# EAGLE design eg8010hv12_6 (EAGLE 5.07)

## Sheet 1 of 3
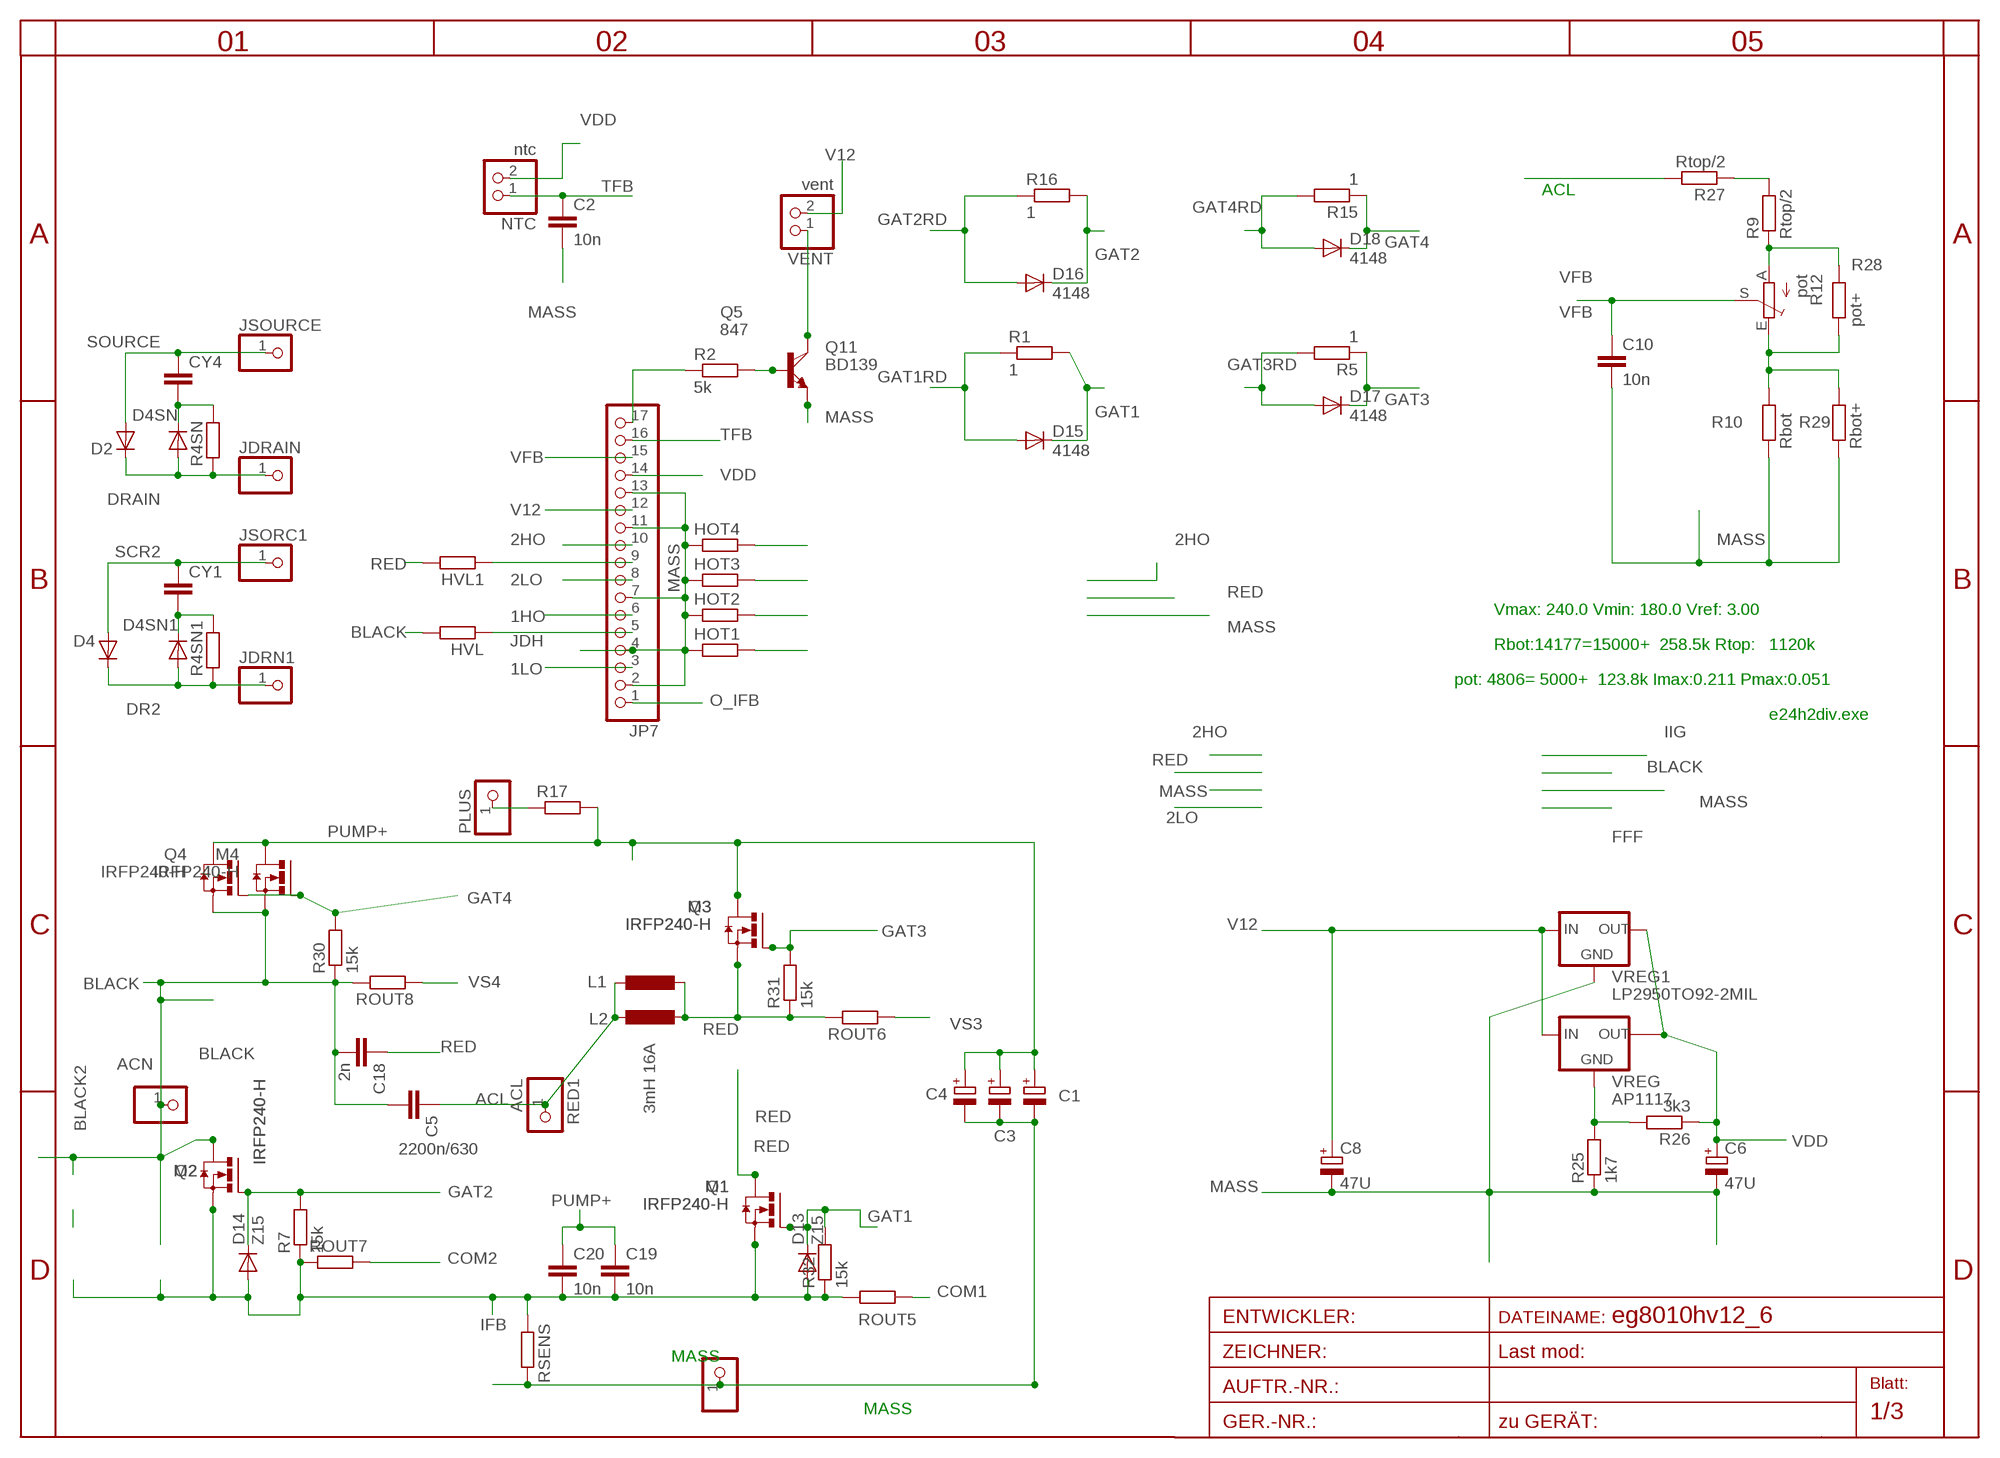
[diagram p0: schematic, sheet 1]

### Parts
BLACK2  ACN  PINHD-1X12MM3  [1X2MM3]
C1  CPOL-EUE5-13  [E5-13]
C2  10n  C-EUC0805  [C0805]
C3  CPOL-EUE5-13  [E5-13]
C4  CPOL-EUE5-13  [E5-13]
C5  2200n/630  C-EU275-173X316  [C275-173X316]
C6  47U  CPOL-EUSMCA  [SMC_A]
C8  47U  CPOL-EUSMCA  [SMC_A]
C10  10n  C-EUC0805  [C0805]
C18  2n  C-EU050-024X044  [C050-024X044]
C19  10n  C-EU050-024X044  [C050-024X044]
C20  10n  C-EU050-024X044  [C050-024X044]
CY1  CXXC10B5  [XC10B5]
CY4  CXXC10B5  [XC10B5]
D2  DIODE-TO220V  [TO220ACS]
D4  DIODE-TO220V  [TO220ACS]
D4SN  DIODE-P1-10  [P1-10]
D4SN1  DIODE-P1-10  [P1-10]
D13  Z15  DIODE-MINIMELF  [MINIMELF]
D14  Z15  DIODE-MINIMELF  [MINIMELF]
D15  4148  DIODE-MINIMELF  [MINIMELF]
D16  4148  DIODE-MINIMELF  [MINIMELF]
D17  4148  DIODE-MINIMELF  [MINIMELF]
D18  4148  DIODE-MINIMELF  [MINIMELF]
HOT1  R-EU_R0805  [R0805]
HOT2  R-EU_R0805  [R0805]
HOT3  R-EU_R0805  [R0805]
HOT4  R-EU_R0805  [R0805]
HVL  R-EU_R1005  [R1005]
HVL1  R-EU_R1005  [R1005]
JDRAIN  PINHD-1X11MM0  [1X1MM0]
JDRN1  PINHD-1X11MM0  [1X1MM0]
JP7  PINHD-1X17  [1X17]
JSORC1  PINHD-1X11MM0  [1X1MM0]
JSOURCE  PINHD-1X11MM0  [1X1MM0]
L1  L-EU4.13  [0204/13]
L2  3mH 16A  L-EURNG  [RING]
M1  IRFP240-H  [TO247BH]
M2  IRFP240-H  [TO247BH]
M3  IRFP240-H  [TO247BH]
M4  IRFP240-H  [TO247BH]
MINUS  PINHD-1X12MM3  [1X2MM3]
NTC  ntc  PINHD-1X2STR  [1X02]
PLUS  PINHD-1X12MM3  [1X2MM3]
Q1  IRFP240-H  [TO247BH]
Q2  IRFP240-H  [TO247BH]
Q3  IRFP240-H  [TO247BH]
Q4  IRFP240-H  [TO247BH]
Q5  847  BC847SMD  [SOT23]
Q11  BD139  [TO126AV]
R1  1  R-EU_R2512  [R2512]
R2  5k  R-EU_R0805  [R0805]
R4SN  R-EU_0207/10  [0207/10]
R4SN1  R-EU_0207/10  [0207/10]
R5  1  R-EU_R2512  [R2512]
R7  15k  R-EU_R1206  [R1206]
R9  Rtop/2  R-EU_R1206  [R1206]
R10  Rbot  R-EU_R0805  [R0805]
R12  pot  TRIM_EU-B64Y  [B64Y]
R15  1  R-EU_R2512  [R2512]
R16  1  R-EU_R2512  [R2512]
R17  R-EU_0309/10  [0309/10]
R25  1k7  R-EU_R0805  [R0805]
R26  3k3  R-EU_R0805  [R0805]
R27  Rtop/2  R-EU_R1206  [R1206]
R28  pot+  R-EU_R0805  [R0805]
R29  Rbot+  R-EU_R0805  [R0805]
R30  15k  R-EU_R1206  [R1206]
R31  15k  R-EU_R1206  [R1206]
R32  15k  R-EU_R1206  [R1206]
RED1  ACL  PINHD-1X12MM3  [1X2MM3]
ROUT5  R-EU_R2512  [R2512]
ROUT6  R-EU_R2512  [R2512]
ROUT7  R-EU_R2512  [R2512]
ROUT8  R-EU_R2512  [R2512]
RSENS  R-EU_WIRE  [WIRE]
VENT  vent  PINHD-1X2STR  [1X02]
VREG  AP1117  [SOT223]
VREG1  LP2950TO92-2MIL  [TO92-2MIL]

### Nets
1HO: HOT2.2 JP7.6 ; also sheet 3
1LO: HOT1.2 JP7.3 ; also sheet 3
2HO: HOT4.2 JP7.10 ; also sheet 3
2LO: HOT3.2 JP7.8 ; also sheet 3
ACL: C5.1 L1.1 L2.2 R27.2 RED1.1
BLACK: BLACK2.1 C5.2 C18.2 HVL.2 M2.D M4.S Q2.D Q4.S R30.1 ROUT8.2
COM1: ROUT5.1 ; also sheet 3
COM2: ROUT7.2 ; also sheet 3
DFG: HVL1.1 JP7.9
DR2: D4.C D4SN1.A JDRN1.1 R4SN1.1
DRAIN: D2.C D4SN.A JDRAIN.1 R4SN.1
GAT1: D13.C D15.C M1.G Q1.G R1.2 R32.2
GAT1RD: D15.A R1.1 ; also sheet 3
GAT2: D14.C D16.C M2.G Q2.G R7.2 R16.2
GAT2RD: D16.A R16.1 ; also sheet 3
GAT3: D17.C M3.G Q3.G R5.1 R31.2
GAT3RD: D17.A R5.2 ; also sheet 3
GAT4: D18.C M4.G Q4.G R15.1 R30.2
GAT4RD: D18.A R15.2 ; also sheet 3
IFB: C19.2 C20.2 D13.A D14.A M1.S M2.S Q1.S Q2.S R7.1 R32.1 ROUT5.2 ROUT7.1 RSENS.1 ; also sheet 2,3
JDH: HVL.1 JP7.5
MASS: C1.- C2.2 C3.- C4.- C6.- C8.- C10.2 HOT1.1 HOT2.1 HOT3.1 HOT4.1 JP7.2 JP7.4 JP7.7 JP7.11 JP7.13 MINUS.1 Q5.2(E) Q11.E R10.1 R25.1 R29.1 RSENS.2 VREG1.2(GND) ; also sheet 2,3
N$1: Q5.3(C) Q11.C VENT.1
N$2: Q5.1(B) Q11.B R2.2
N$3: JP7.17 R2.1
N$5: PLUS.1 R17.1
N$17: R25.2 R26.2 VREG.1(GND)
N$23: R9.2 R27.1
N$29: R10.2 R12.E R28.1 R29.2
N$30: R9.1 R12.A R28.2
O_IFB: JP7.1 ; also sheet 3
PUMP+: C1.+ C3.+ C4.+ C19.1 C20.1 M3.D M4.D Q3.D Q4.D R17.2 ; also sheet 2
RED: C18.1 HVL1.2 L1.2 L2.1 M1.D M3.S Q1.D Q3.S R31.1 ROUT6.2
SCR2: CY1.1 D4.A JSORC1.1
SNUB1: CY1.2 D4SN1.C R4SN1.2
SNUB2: CY4.2 D4SN.C R4SN.2
SOURCE: CY4.1 D2.A JSOURCE.1
TFB: C2.1 JP7.16 NTC.1 ; also sheet 2
V12: C8.+ JP7.12 VENT.2 VREG1.3(IN) VREG.3(IN) ; also sheet 2,3
VDD: C6.+ JP7.14 NTC.2 R26.1 VREG1.1(OUT) VREG.4(TAB) ; also sheet 2,3
VFB: C10.1 JP7.15 R12.S ; also sheet 2
VS3: ROUT6.1 ; also sheet 3
VS4: ROUT8.1 ; also sheet 3
Unconnected: VREG.2(OUT)

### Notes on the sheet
- Vmax: 240.0 Vmin: 180.0 Vref: 3.00
- Rbot:14177=15000+  258.5k Rtop:   1120k
- pot: 4806= 5000+  123.8k Imax:0.211 Pmax:0.051
- e24h2div.exe

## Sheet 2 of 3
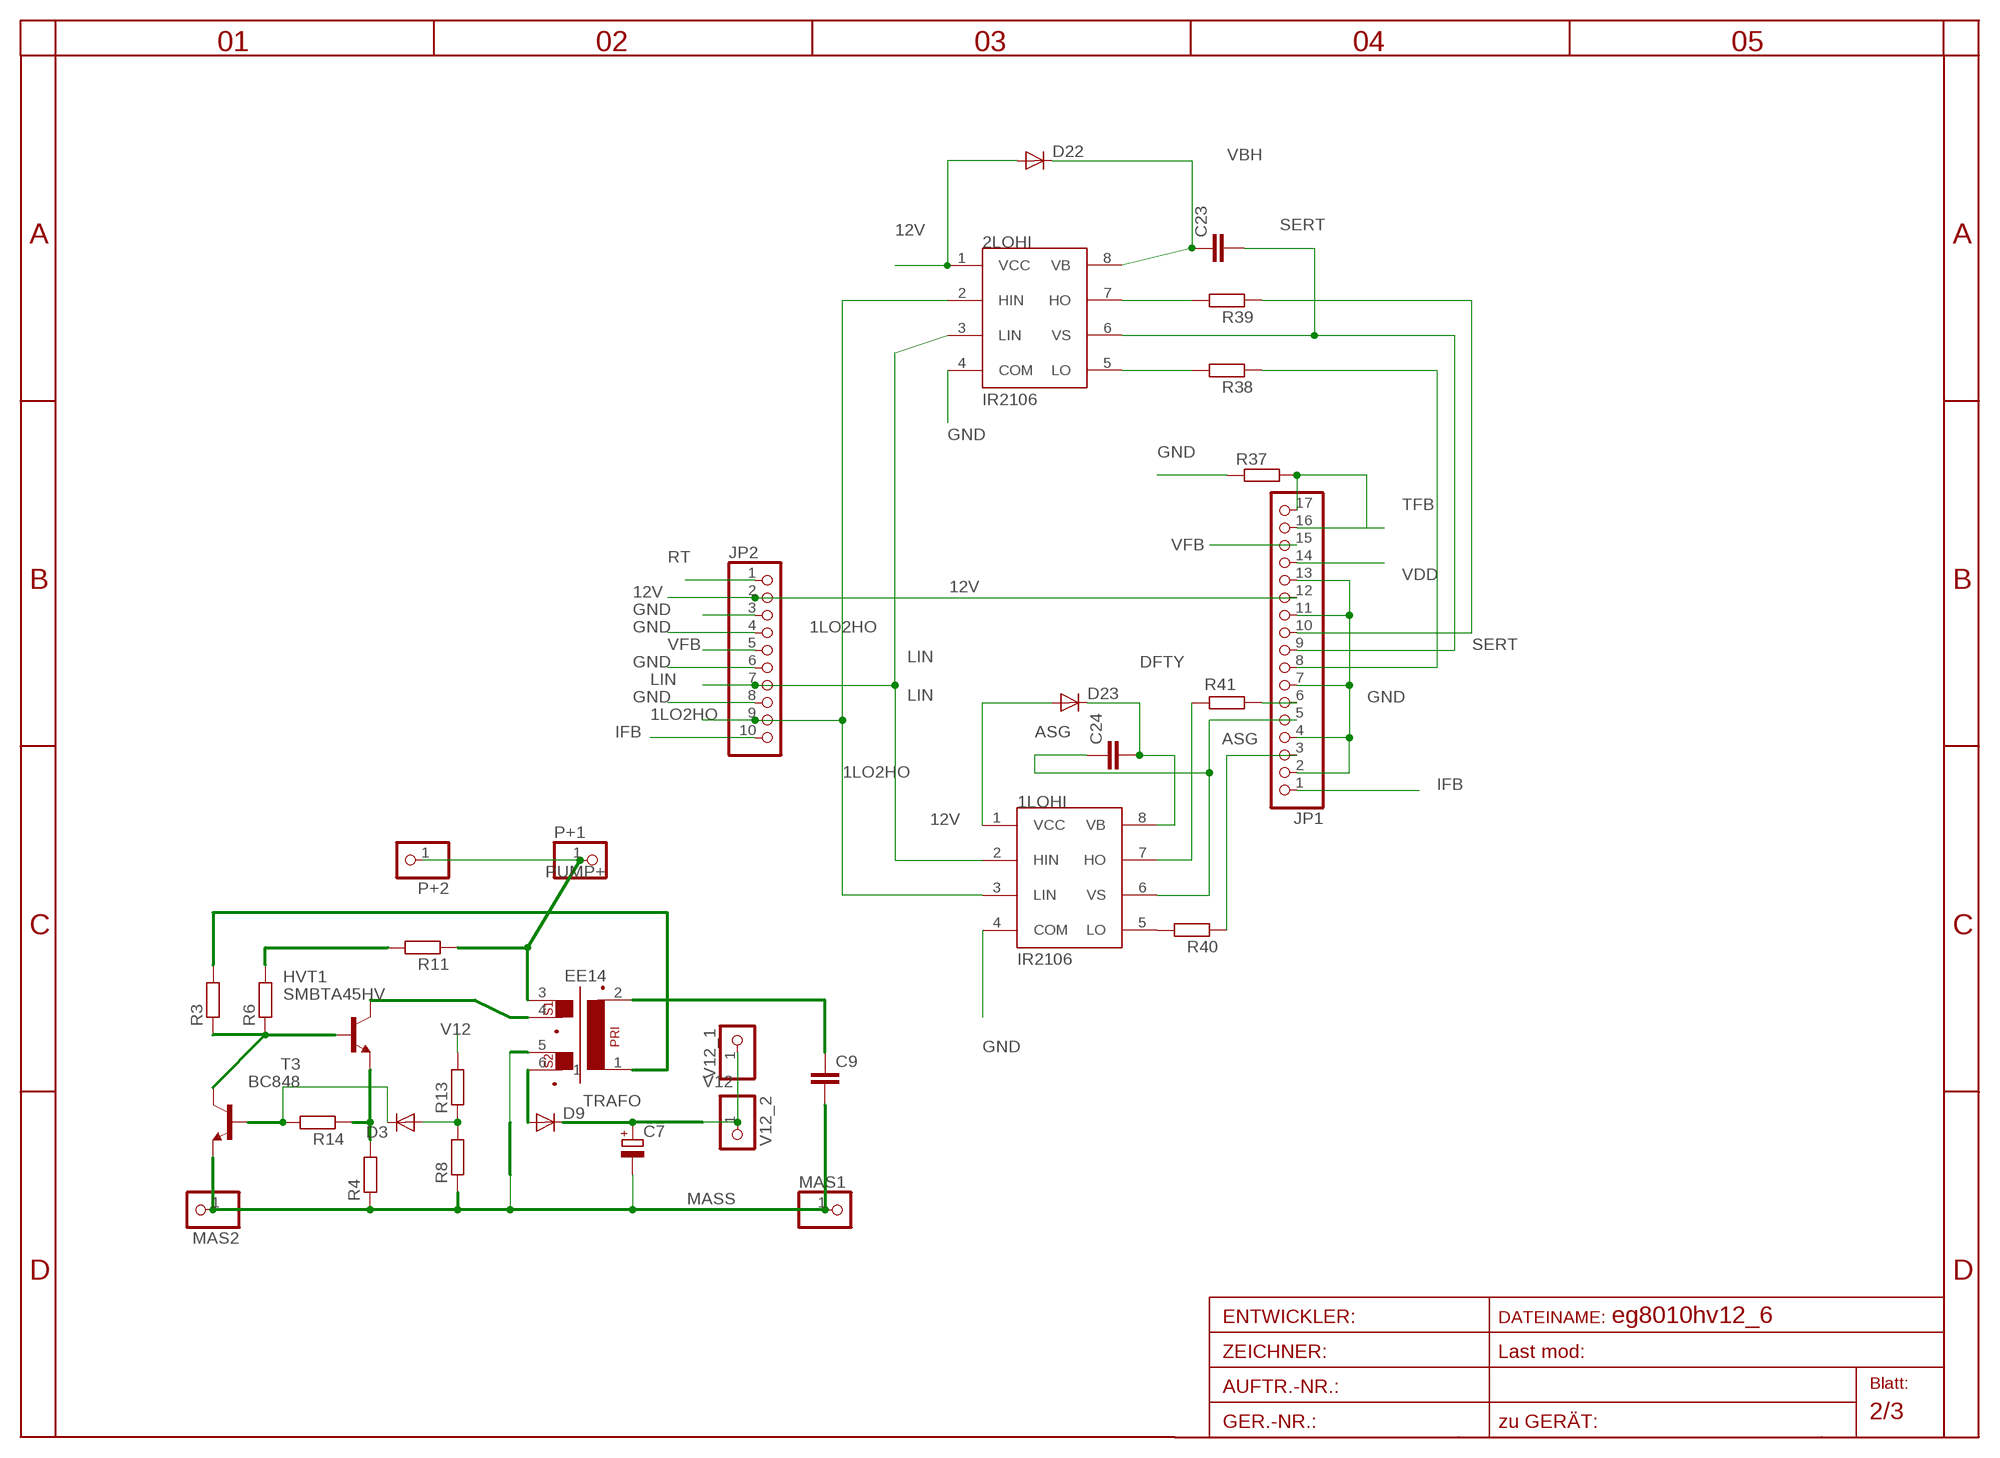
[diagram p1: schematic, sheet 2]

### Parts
1LOHI  IR2106  [SO8-5]
2LOHI  IR2106  [SO8-5]
C7  CPOL-EUSMCA  [SMC_A]
C9  C-EUC0805  [C0805]
C23  C-EUC1206  [C1206]
C24  C-EUC1206  [C1206]
D3  DIODE-MINIMELF  [MINIMELF]
D9  DIODE-SMA-DO214  [SMA-DO214AC]
D22  DIODE-SMA-DO214  [SMA-DO214AC]
D23  DIODE-SMA-DO214  [SMA-DO214AC]
HVT1  SMBTA45HV  [SOT23HV]
JP1  PINHD-1X17  [1X17]
JP2  PINHD-1X100X05  [1X10]
MAS1  PINHD-1X11X0.4  [1X01]
MAS2  PINHD-1X11X0.4  [1X01]
P+1  PINHD-1X11X0.4  [1X01]
P+2  PINHD-1X11X0.4  [1X01]
R3  R-EU_R0805  [R0805]
R4  R-EU_R0805  [R0805]
R6  R-EU_R1206  [R1206]
R8  R-EU_R0805  [R0805]
R11  R-EU_R1206  [R1206]
R13  R-EU_R0805  [R0805]
R14  R-EU_R0805  [R0805]
R37  R-EU_0204/2V  [0204V]
R38  R-EU_R1206  [R1206]
R39  R-EU_R1206  [R1206]
R40  R-EU_R1206  [R1206]
R41  R-EU_R1206  [R1206]
T3  BC848  [SOT23]
TRAFO  EE14  [EE14]
V12_1  PINHD-1X11X0.4  [1X01]
V12_2  PINHD-1X11X0.4  [1X01]

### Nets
1LO2HO: 1LOHI.3(LIN) 2LOHI.2(HIN) JP2.9
12V: 1LOHI.1(VCC) 2LOHI.1(VCC) D22.A D23.A JP1.12 JP2.2
A: D9.A TRAFO.6
ASG: 1LOHI.6(VS) C24.1 JP1.5
B1C2: HVT1.1(B) R3.1 R6.1 T3.C
BT1: D3.C R14.2 T3.B
C1: HVT1.3(C) TRAFO.4
DFTY: 1LOHI.8(VB) C24.2 D23.K(C)
EB: HVT1.2(E) R4.2 R14.1
GND: 1LOHI.4(COM) 2LOHI.4(COM) JP1.2 JP1.4 JP1.7 JP1.11 JP1.13 JP2.3 JP2.4 JP2.6 JP2.8 R37.1
IFB: JP1.1 JP2.10 ; also sheet 1,3
LIN: 1LOHI.2(HIN) 2LOHI.3(LIN) JP2.7
MASS: C7.- C9.2 MAS1.1 MAS2.1 R4.1 R8.1 T3.E TRAFO.5 ; also sheet 1,3
N$6: R3.2 TRAFO.1
N$7: C9.1 TRAFO.2
N$8: R6.2 R11.2
N$10: D3.A R8.2 R13.1
N$15: JP1.3 R40.1
N$19: 1LOHI.7(HO) R41.2
N$21: JP1.8 R38.1
N$27: JP1.10 R39.1
N$32: 2LOHI.5(LO) R38.2
N$33: 2LOHI.7(HO) R39.2
N$34: JP1.6 R41.1
N$35: 1LOHI.5(LO) R40.2
PUMP+: P+1.1 P+2.1 R11.1 TRAFO.3 ; also sheet 1
RT: JP2.1
SERT: 2LOHI.6(VS) C23.2 JP1.9
TFB: JP1.16 JP1.17 R37.2 ; also sheet 1
V12: C7.+ D9.K(C) R13.2 V12_1.1 V12_2.1 ; also sheet 1,3
VBH: 2LOHI.8(VB) C23.1 D22.K(C)
VDD: JP1.14 ; also sheet 1,3
VFB: JP1.15 JP2.5 ; also sheet 1

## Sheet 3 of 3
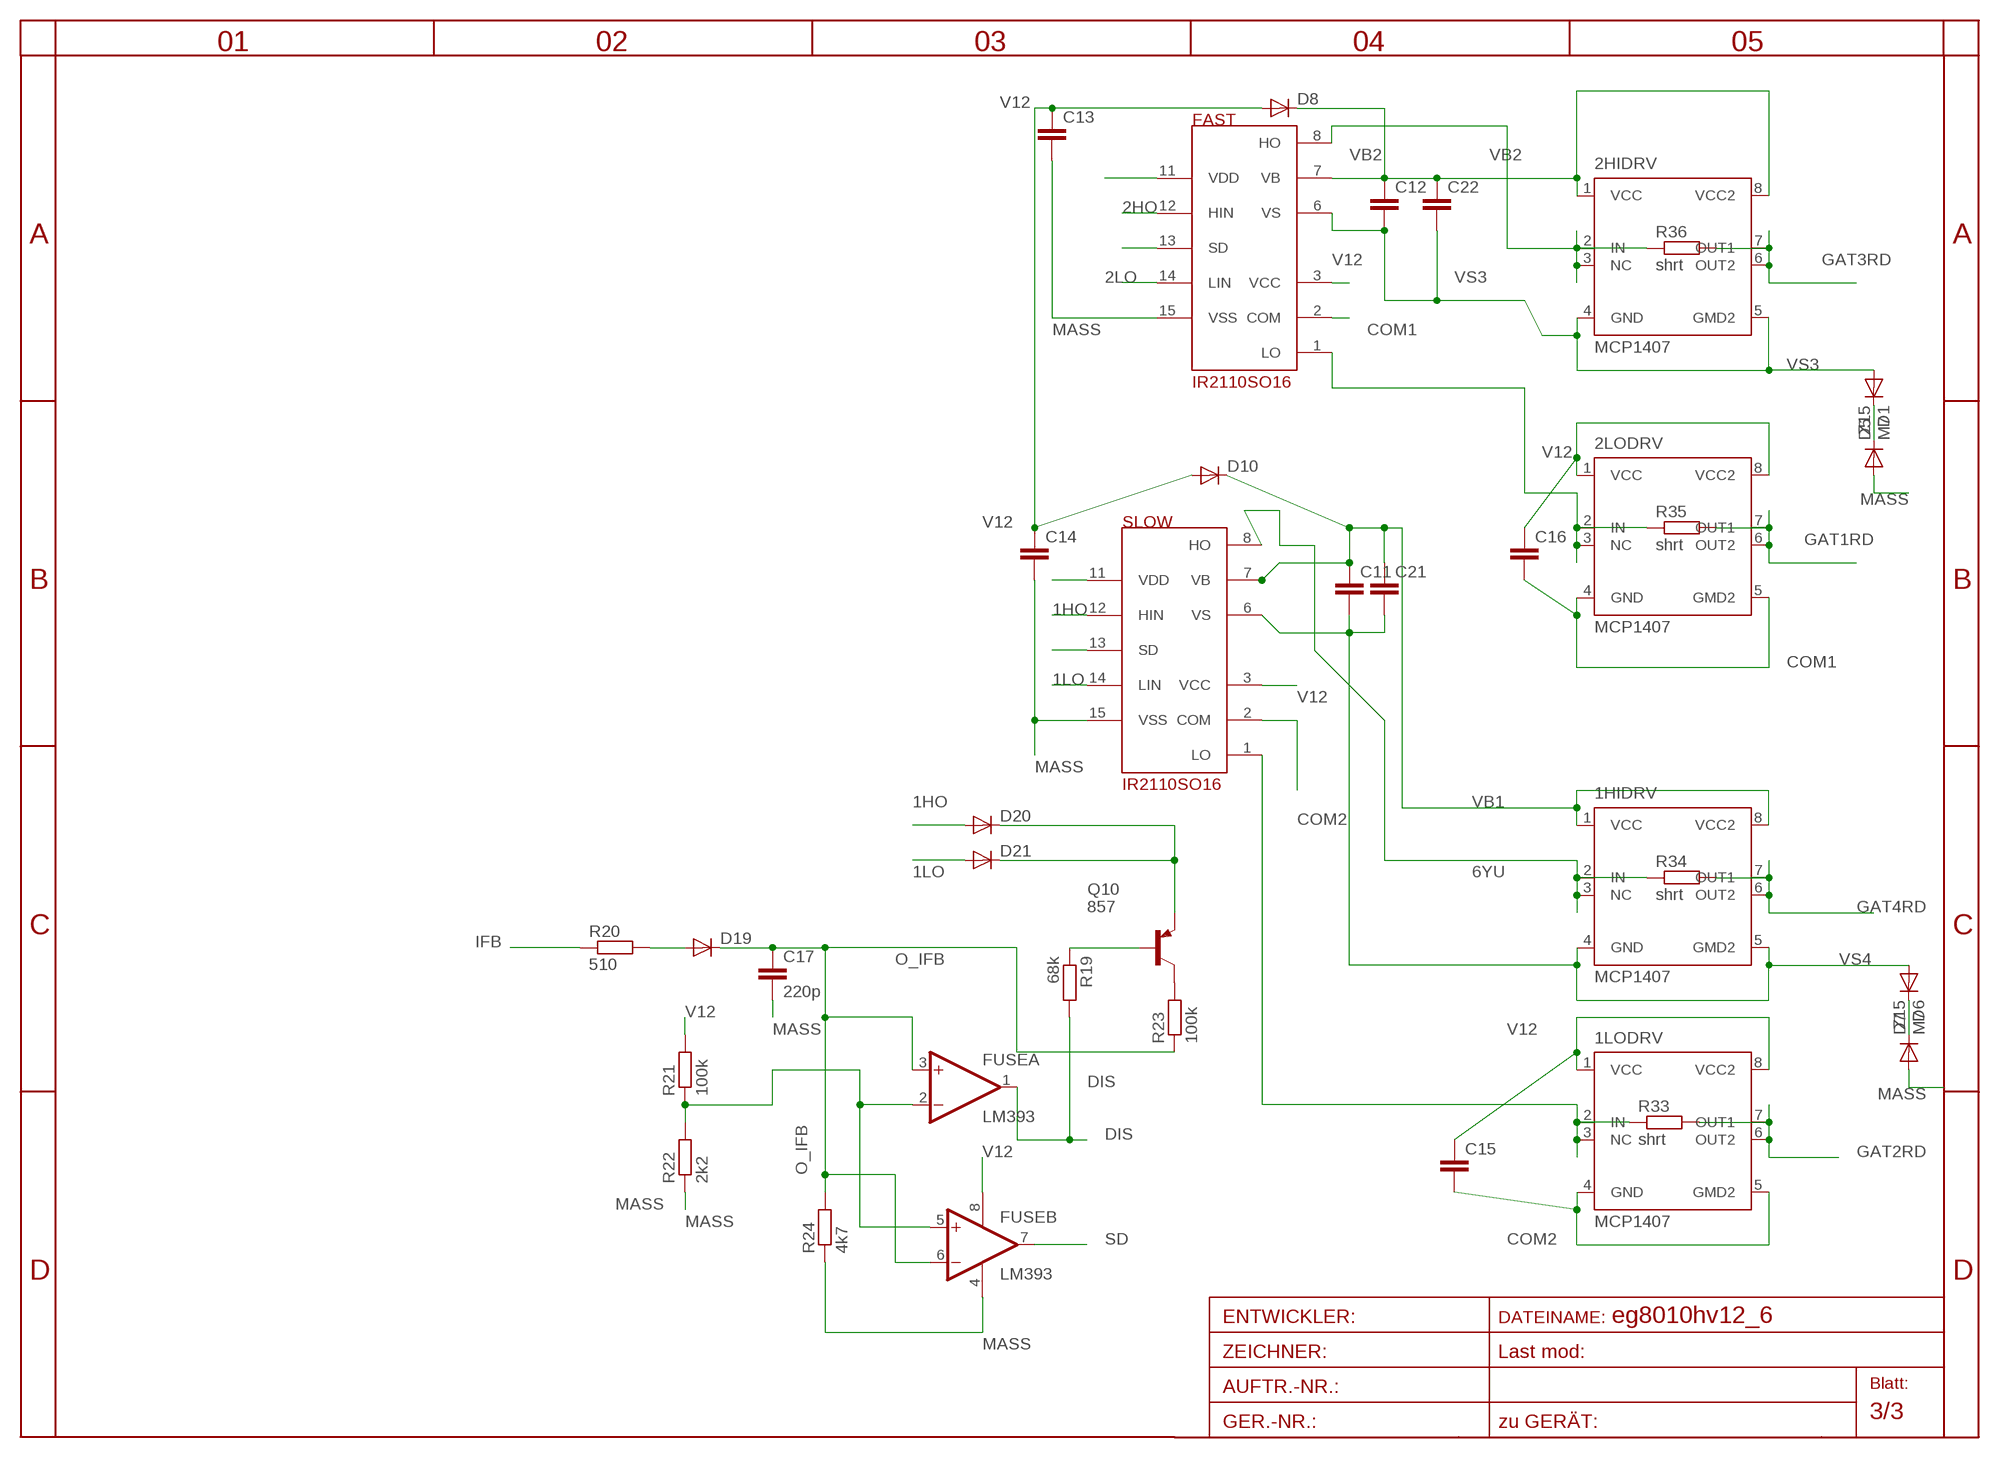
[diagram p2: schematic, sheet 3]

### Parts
1HIDRV  MCP1407  [SO-08M]
1LODRV  MCP1407  [SO-08M]
2HIDRV  MCP1407  [SO-08M]
2LODRV  MCP1407  [SO-08M]
C11  C-EUC058MLCC  [C058-020X040]
C12  C-EUC058MLCC  [C058-020X040]
C13  C-EUC1206  [C1206]
C14  C-EUC1206  [C1206]
C15  C-EUC1206  [C1206]
C16  C-EUC1206  [C1206]
C17  220p  C-EUC0805  [C0805]
C21  C-EUC1206  [C1206]
C22  C-EUC1206  [C1206]
D1  Z15  DIODE-MINIMELF  [MINIMELF]
D5  M7  DIODE-SMA-DO214  [SMA-DO214AC]
D6  Z15  DIODE-MINIMELF  [MINIMELF]
D7  M7  DIODE-SMA-DO214  [SMA-DO214AC]
D8  DIODE-SMA-DO214  [SMA-DO214AC]
D10  DIODE-SMA-DO214  [SMA-DO214AC]
D19  DIODE-SOT23  [SOT23]
D20  DIODE-SOT23  [SOT23]
D21  DIODE-SOT23  [SOT23]
FAST  IR2110SO16  [SO16DW]
FUSE  LM393  LM358D  [SO08]
Q10  857  BC857ALT1SMD  [SOT23-BEC]
R19  68k  R-EU_R0805  [R0805]
R20  510  R-EU_R0805  [R0805]
R21  100k  R-EU_R0805  [R0805]
R22  2k2  R-EU_R0805  [R0805]
R23  100k  R-EU_R0805  [R0805]
R24  4k7  R-EU_R0805  [R0805]
R33  shrt  R-EU_R1206  [R1206]
R34  shrt  R-EU_R1206  [R1206]
R35  shrt  R-EU_R1206  [R1206]
R36  shrt  R-EU_R1206  [R1206]
SLOW  IR2110SO16  [SO16DW]

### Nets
1HO: D20.1(A) SLOW.12(HIN) ; also sheet 1
1LO: D21.1(A) SLOW.14(LIN) ; also sheet 1
2HO: FAST.12(HIN) ; also sheet 1
2LO: FAST.14(LIN) ; also sheet 1
6YU: 1HIDRV.2(IN) 1HIDRV.3(NC) R34.1 SLOW.8(HO)
COM1: 2LODRV.4(GND) 2LODRV.5(GMD2) C16.2 FAST.2(COM) ; also sheet 1
COM2: 1LODRV.4(GND) 1LODRV.5(GMD2) C15.2 SLOW.2(COM) ; also sheet 1
DIS: FUSE.1(A:OUT) R19.2
ET: 1LODRV.2(IN) 1LODRV.3(NC) R33.1 SLOW.1(LO)
GAT1RD: 2LODRV.6(OUT2) 2LODRV.7(OUT1) R35.2 ; also sheet 1
GAT2RD: 1LODRV.6(OUT2) 1LODRV.7(OUT1) R33.2 ; also sheet 1
GAT3RD: 2HIDRV.6(OUT2) 2HIDRV.7(OUT1) R36.2 ; also sheet 1
GAT4RD: 1HIDRV.6(OUT2) 1HIDRV.7(OUT1) R34.2 ; also sheet 1
IFB: R20.1 ; also sheet 1,2
MASS: C13.2 C14.2 C17.2 D5.A D7.A FAST.15(VSS) FUSE.4(P:V-) R22.1 R24.1 SLOW.15(VSS) ; also sheet 1,2
N$9: FUSE.2(A:-IN) FUSE.5(B:+IN) R21.1 R22.2
N$12: 2HIDRV.2(IN) 2HIDRV.3(NC) FAST.8(HO) R36.1
N$14: D19.1(A) R20.2
N$16: 2LODRV.2(IN) 2LODRV.3(NC) FAST.1(LO) R35.1
N$18: D20.3(C) D21.3(C) Q10.E
N$20: D1.C D5.K(C)
N$24: D6.C D7.K(C)
N$25: Q10.B R19.1
N$26: Q10.C R23.2
O_IFB: C17.1 D19.3(C) FUSE.3(A:+IN) FUSE.6(B:-IN) R23.1 R24.2 ; also sheet 1
SD: FAST.13(SD) FUSE.7(B:OUT) SLOW.13(SD)
V12: 1LODRV.1(VCC) 1LODRV.8(VCC2) 2LODRV.1(VCC) 2LODRV.8(VCC2) C13.1 C14.1 C15.1 C16.1 D8.A D10.A FAST.3(VCC) FUSE.8(P:V+) R21.2 SLOW.3(VCC) ; also sheet 1,2
VB1: 1HIDRV.1(VCC) 1HIDRV.8(VCC2) C11.1 C21.1 D10.K(C) SLOW.7(VB)
VB2: 2HIDRV.1(VCC) 2HIDRV.8(VCC2) C12.1 C22.1 D8.K(C) FAST.7(VB)
VDD: FAST.11(VDD) SLOW.11(VDD) ; also sheet 1,2
VS3: 2HIDRV.4(GND) 2HIDRV.5(GMD2) C12.2 C22.2 D1.A FAST.6(VS) ; also sheet 1
VS4: 1HIDRV.4(GND) 1HIDRV.5(GMD2) C11.2 C21.2 D6.A SLOW.6(VS) ; also sheet 1

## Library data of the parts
1HIDRV 1LODRV 2HIDRV 2LODRV = microchip:MCP1407
1LOHI 2LOHI = irf-2:IR2106
BLACK2 JDRAIN JDRN1 JSORC1 JSOURCE MAS1 MAS2 MINUS P+1 P+2 PLUS RED1 V12_1 V12_2 = pinhead:PINHD-1X1: PIN HEADER
C1 C3 C4 C6-C8 = rcl:CPOL-EU: POLARIZED CAPACITOR, European symbol
C2 C5 C9-C24 = rcl:C-EU: CAPACITOR, European symbol
CY1 CY4 = rcl:CX: X CAPACITOR
D1-D4 D4SN D4SN1 D5-D10 D13-D23 = diode:DIODE-: DIODE
FAST SLOW = ir2112:IR2110
FUSE = linear:LM358: OP AMP also LM158; LM258; LM2904 Source: http://cache.national.com/ds/LM/LM158.pdf
HOT1-HOT4 HVL HVL1 R1-R4 R4SN R4SN1 R5-R8 R11 R13-R17 R19-R24 R30-R41 ROUT5-ROUT8 RSENS = rcl:R-EU_: RESISTOR, European symbol
HVT1 = transistor-npn:SMBTA45
JP1 JP7 = pinhead:PINHD-1X17: PIN HEADER
JP2 = pinhead:PINHD-1X10: PIN HEADER
L1 L2 = rcl:L-EU: INDUCTOR, European symbol
M1-M4 Q1-Q4 = transistor-power:IRFP240: HEXFET Power MosFet Source: http://www.irf.com/
NTC VENT = pinhead:PINHD-1X2: PIN HEADER
Q5 = transistor-npn:BC847*: NPN Transistor
Q10 = transistor-pnp:BC857*: PNP Transistror
Q11 = transistor-power:BD139: NPN TRANSISTOR
R9 R10 R25-R29 = rcl-2:R-EU_: RESISTOR, European symbol
R12 = pot:TRIM_EU-: POTENTIOMETER
T3 = transistor:BC848: NPN TRANSISTOR
TRAFO = trafo:EE14
VREG = v-reg:AP1117
VREG1 = v-reg:LP2950?*: Source: http://cache.national.com/ds/LP/LP2950.pdf

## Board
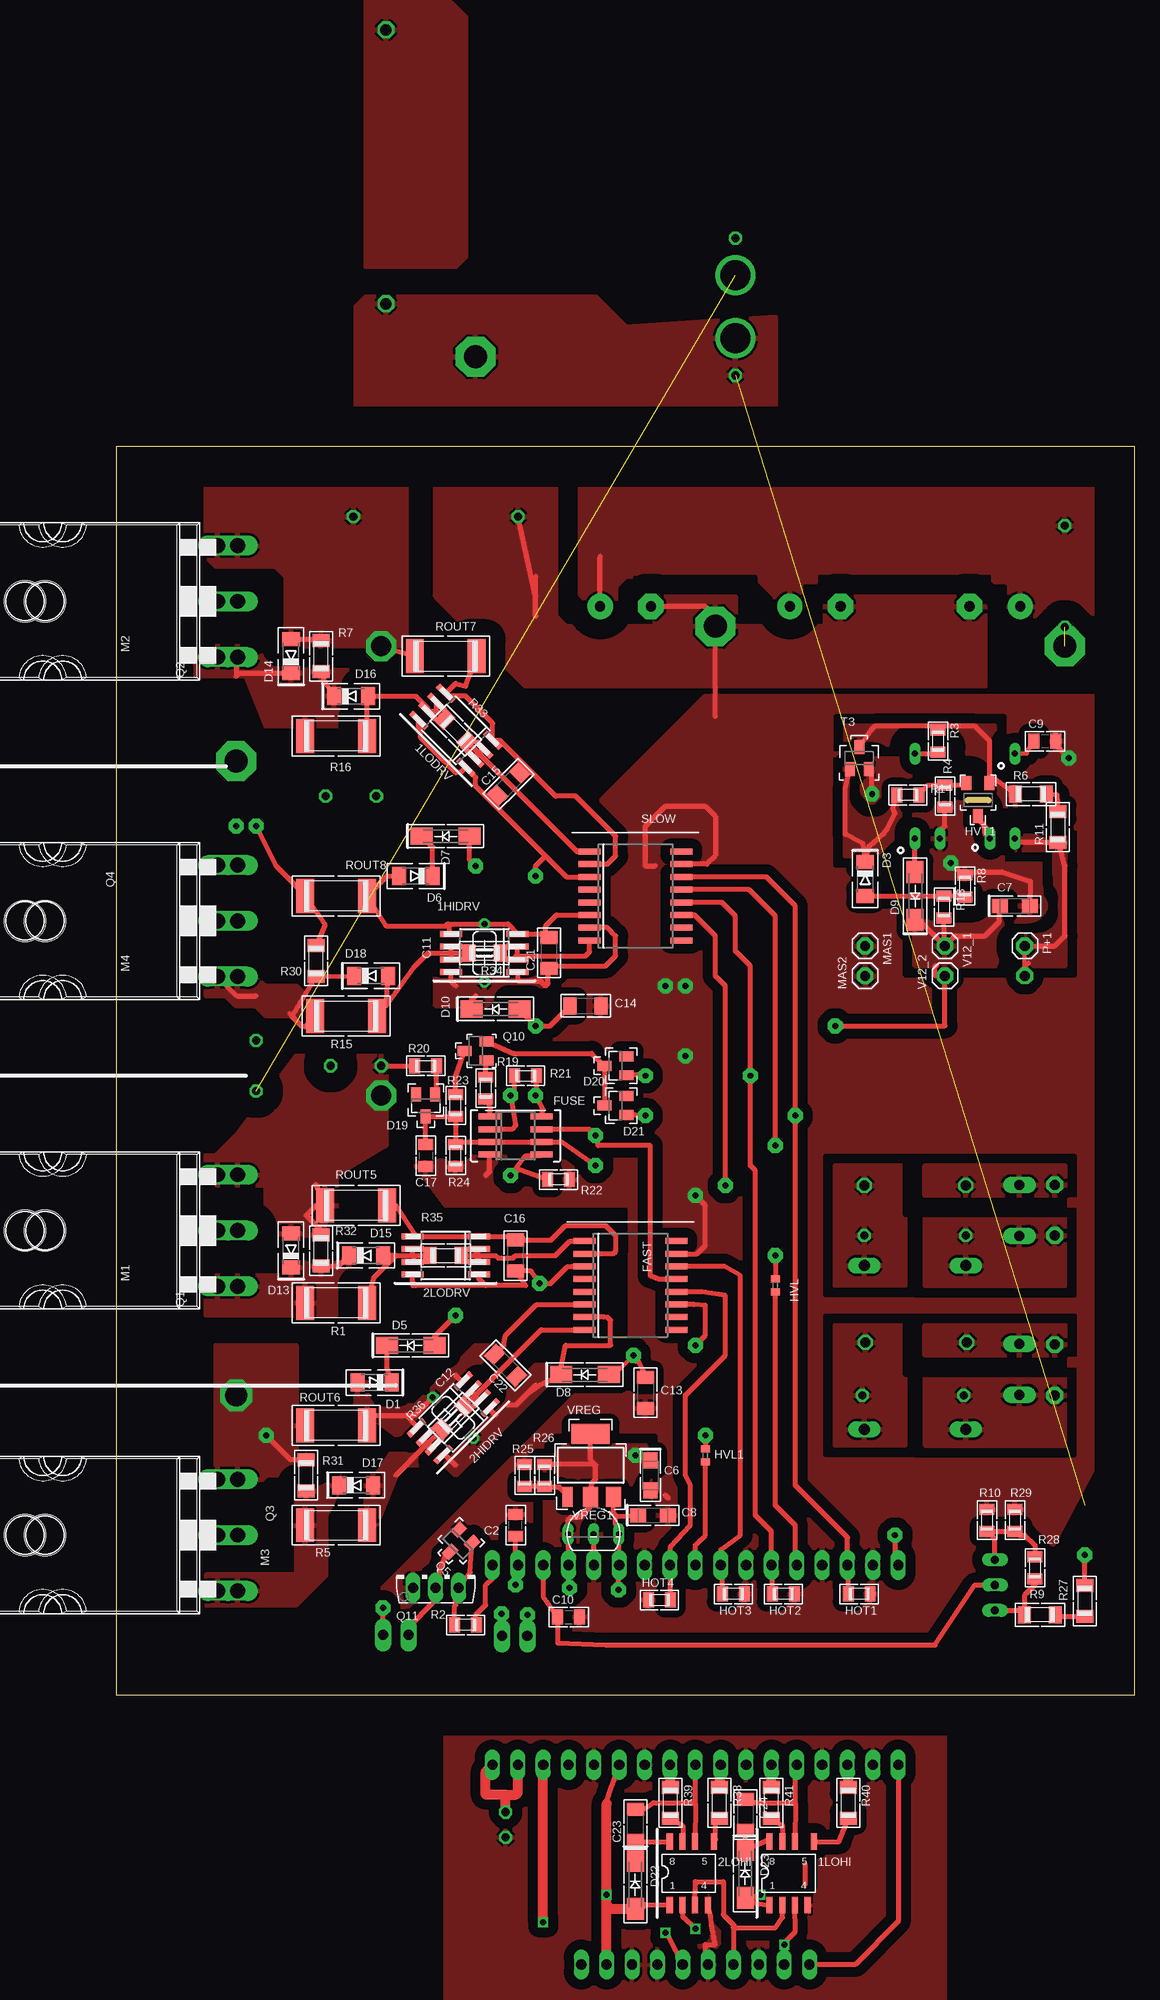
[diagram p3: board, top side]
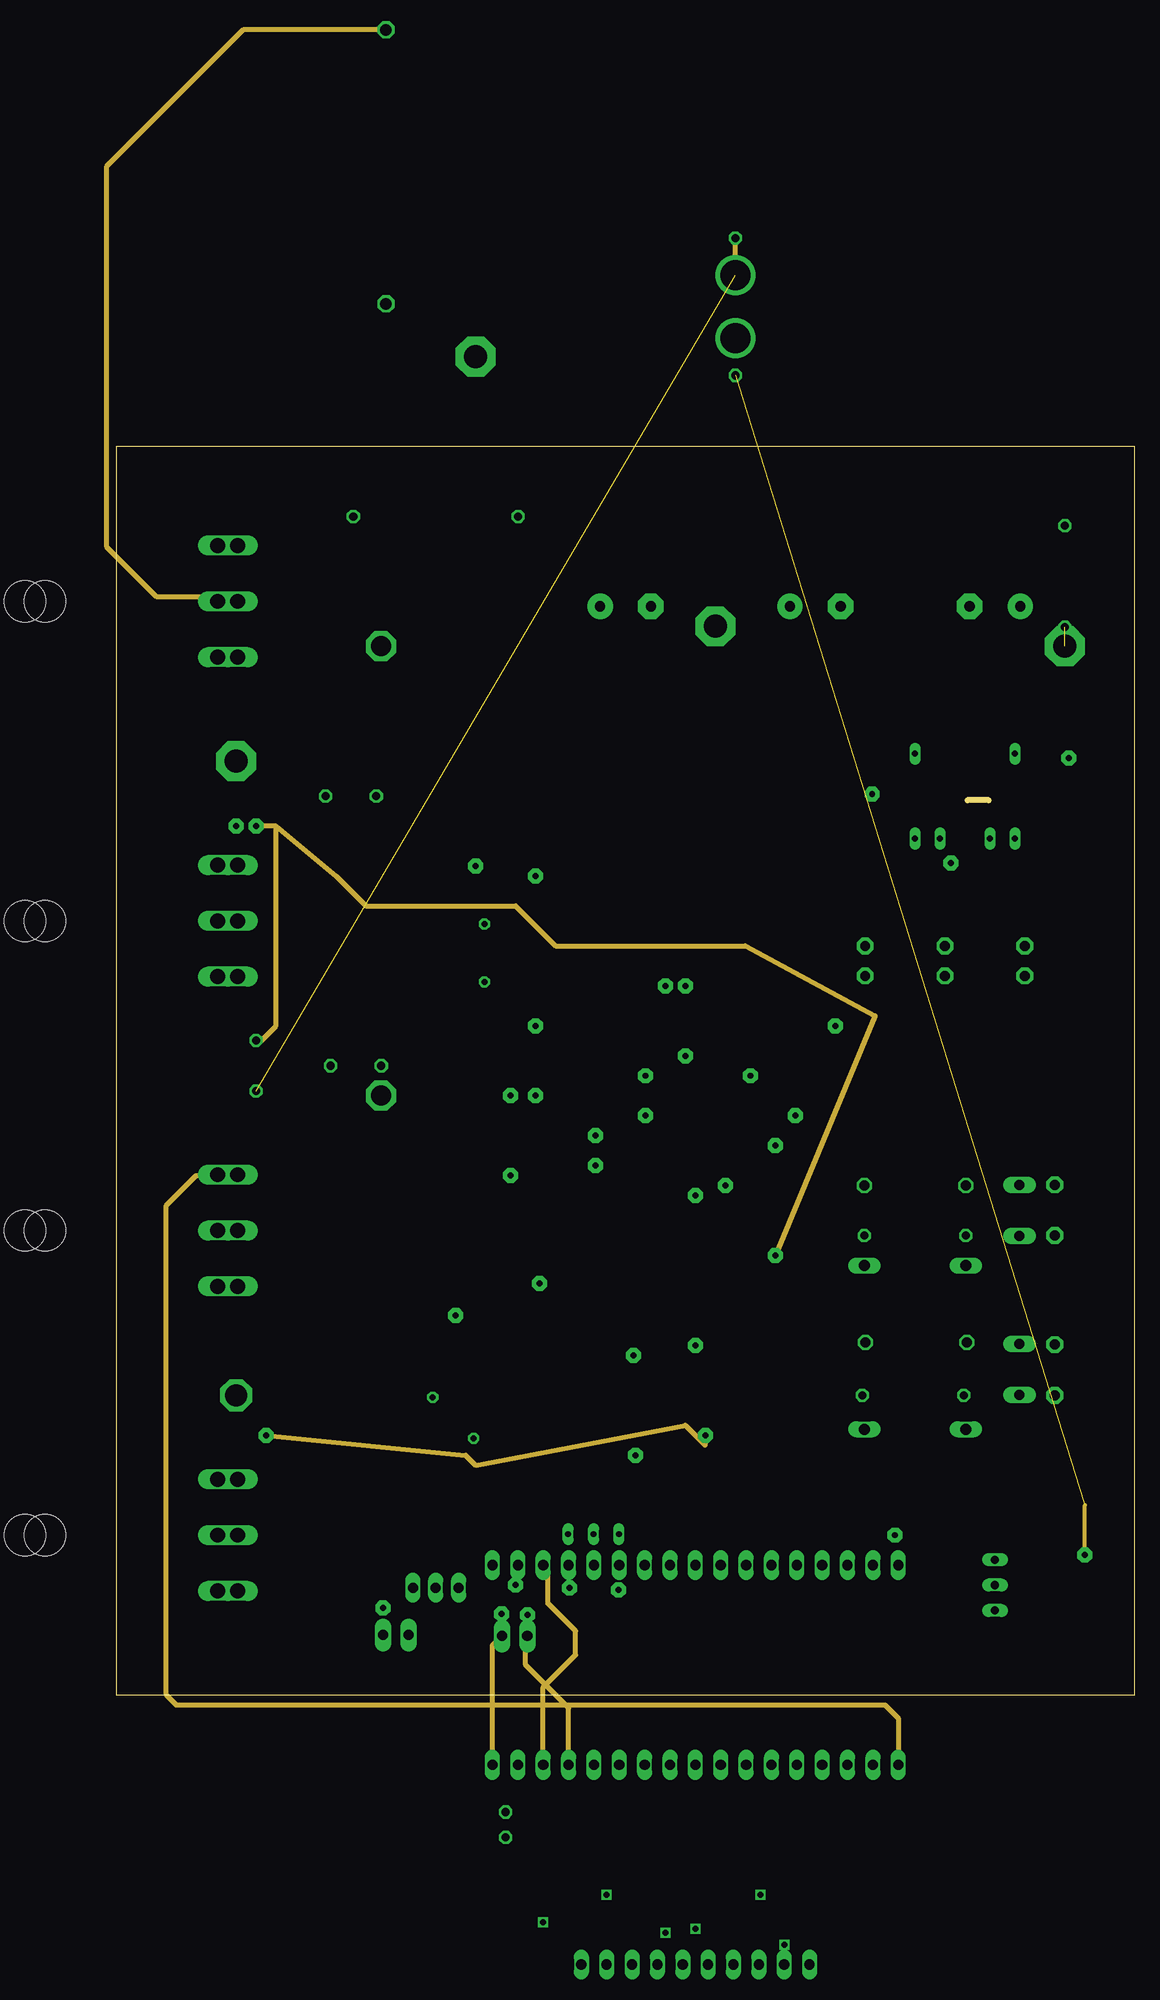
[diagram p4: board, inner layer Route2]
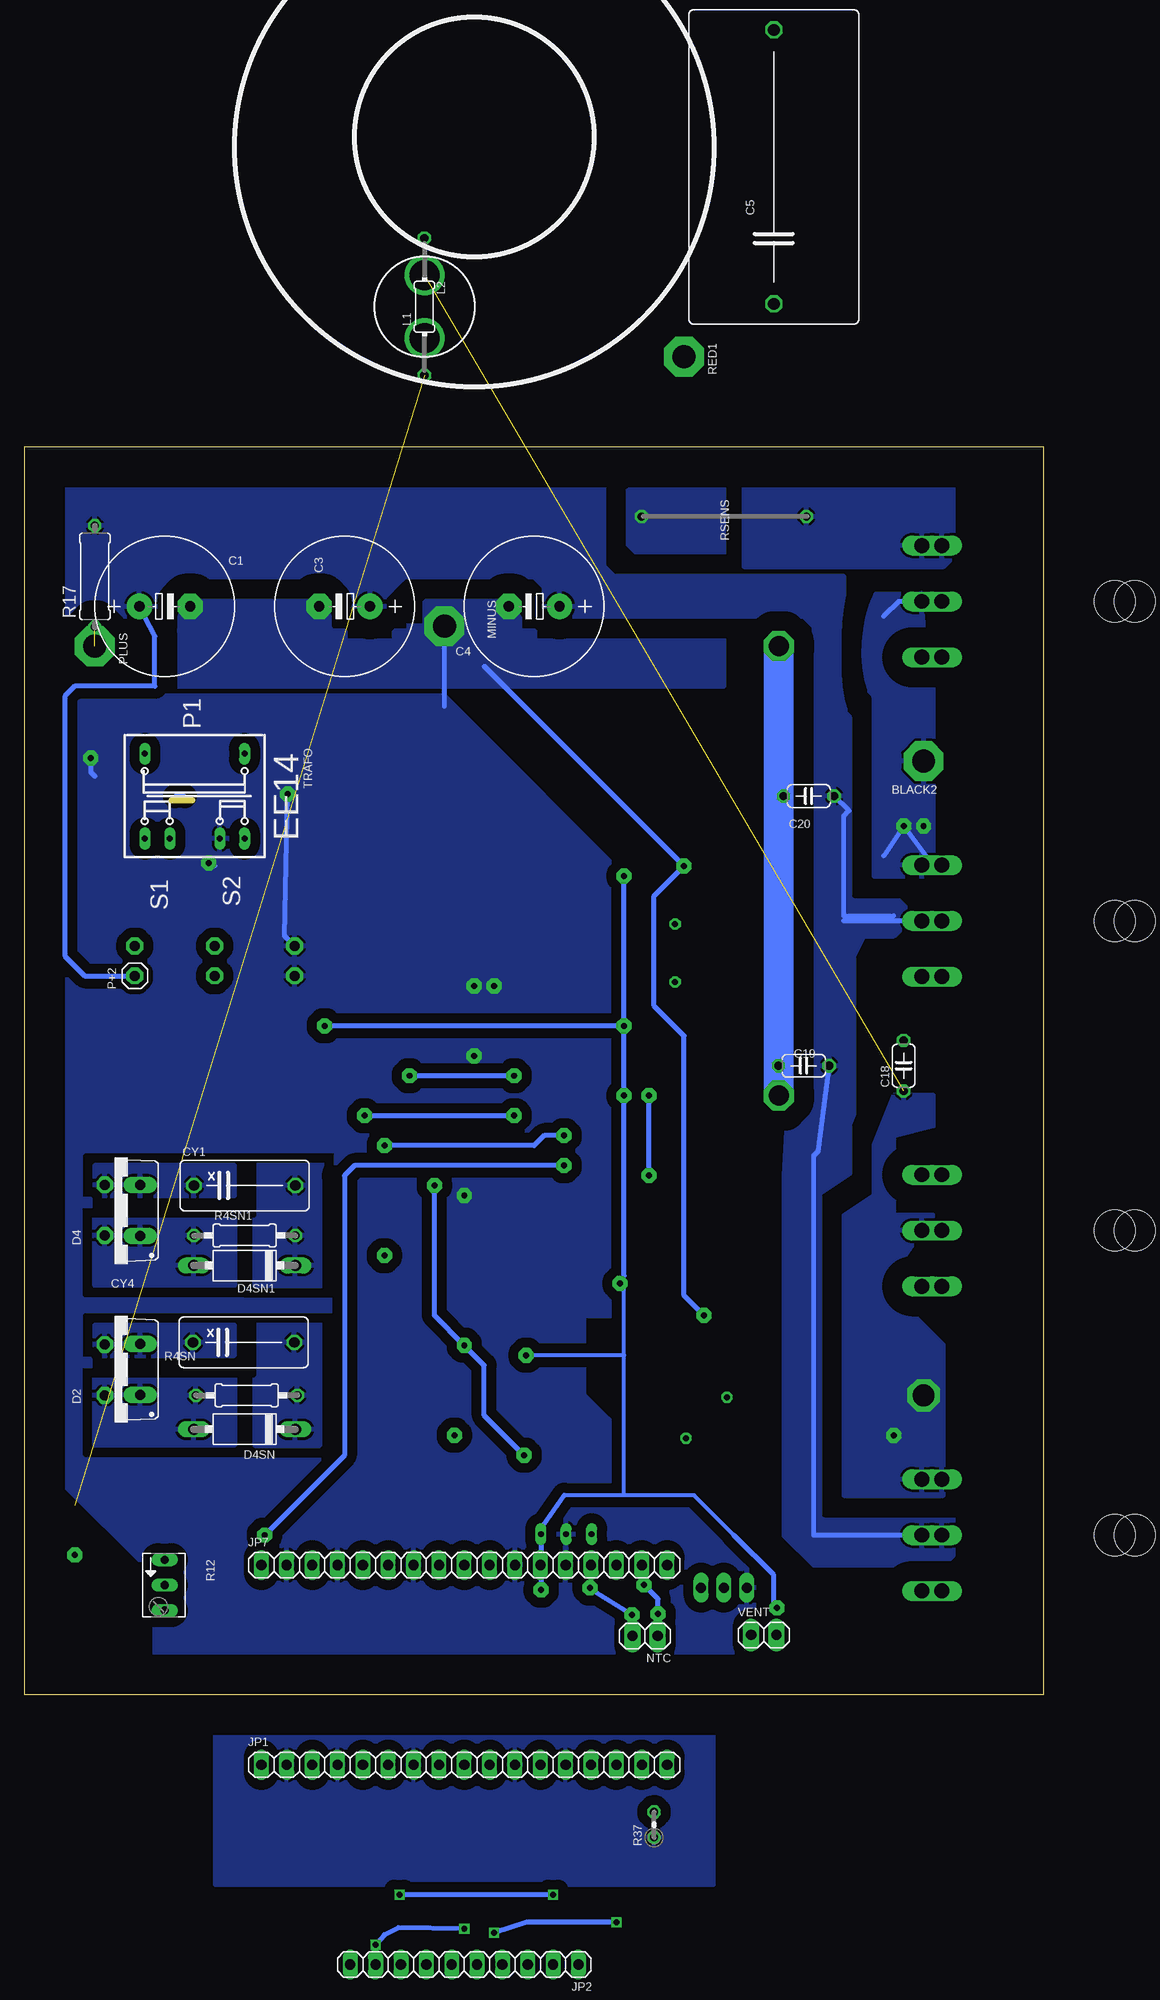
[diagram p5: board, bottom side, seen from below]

Size 102 x 125 mm. Coordinates in mm from the lower left corner, seen from the top.
Outline: 0,0 102,0 102,125 0,125 0,0
Copper layers (1*16): Top 0.035mm / dielectric 1.5mm / Bottom 0.035mm
Design rules "default *": minimum track width 10mil, minimum drill 20mil, track to track 8mil, track to pad 8mil, pad to pad 8mil, via to via 8mil, smd to smd 8mil, copper to edge 4mm, drill to drill 8mil, minimum pad ring 10mil, minimum via ring 8mil, stop-mask expansion 4mil, vias tented up to drill 0mil, thermal gap 10mil

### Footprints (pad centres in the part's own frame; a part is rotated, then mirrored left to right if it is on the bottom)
SO-08M = smd 0.6 x 2.2: 1 -1.905,-3.33; 2 -0.635,-3.33; 3 0.635,-3.33; 4 1.905,-3.33; 5 1.905,3.33; 6 0.635,3.33; 7 -0.635,3.33; 8 -1.905,3.33
SO8-5 = smd 0.61 x 1.626: 1 -1.27,-2.54; 2 0,-2.54; 3 1.27,-2.54; 4 2.54,-2.54; 5 3.175,3.81; 6 1.27,3.81; 7 0,3.81; 8 -1.27,3.81
1X2MM3 = drill 2.3 pad 4 octagon: 1 0,0
E5-13 = drill 1.016 pad 2.54 round: + -2.54,0 | drill 1.016 pad 2.54 octagon: - 2.54,0
C0805 = smd 1.1 x 1.5: 1 -1.1,0; 2 1.1,0
C275-173X316 = drill 1.194 octagon: 1 -13.716,0; 2 13.716,0
SMC_A = smd 1.6 x 1.4: + -1.5,0; - 1.5,0
C058-020X040 = drill 0.6 octagon: 1 -2.9,0; 2 2.9,0
C1206 = smd 1.3 x 1.7: 1 -1.55,0; 2 1.55,0
C050-024X044 = drill 0.813 octagon: 1 -2.54,0; 2 2.54,0
XC10B5 = drill 1.016 octagon: 1 -5.08,0; 2 5.08,0
MINIMELF = smd 1.4 x 1.8: A 1.7,0; C -1.7,0
TO220ACS = drill 1 pad 1.676 long: A 2.54,-2.54; C -2.54,-2.54
P1-10 = drill 1.118 long: A 5.08,0; C -5.08,0
SMA-DO214AC = smd 2.2 x 1.7: A 2.4,0; K -2.4,0
SOT23 = smd 1 x 1.4: 1 -0.95,-1.1; 2 0.95,-1.1; 3 0,1.1
SO16DW = smd 0.6 x 2.2: 1 -4.445,-4.6; 2 -3.175,-4.6; 3 -1.905,-4.6; 4 -0.635,-4.6; 5 0.635,-4.6; 6 1.905,-4.6; 7 3.175,-4.6; 8 4.445,-4.6; 9 4.445,4.6; 10 3.175,4.6; 11 1.905,4.6; 12 0.635,4.6; 13 -0.635,4.6; 14 -1.905,4.6; 15 -3.175,4.6; 16 -4.445,4.6
SO08 = smd 0.6 x 2.2: 1 -1.905,-2.6; 2 -0.635,-2.6; 3 0.635,-2.6; 4 1.905,-2.6; 5 1.905,2.6; 6 0.635,2.6; 7 -0.635,2.6; 8 -1.905,2.6
R0805 = smd 1.1 x 1.5: 1 -1.1,0; 2 1.1,0
R1005 = smd 0.7 x 0.9: 1 -0.65,0; 2 0.65,0
SOT23HV = smd 1 x 1.4: 1 -1.15,-1.7; 2 1.15,-1.7; 3 0,1.6
1X1MM0 = drill 1 pad 1.676 octagon: 1 0,0
1X17 = drill 1.016 long: 1 -20.32,0; 2 -17.78,0; 3 -15.24,0; 4 -12.7,0; 5 -10.16,0; 6 -7.62,0; 7 -5.08,0; 8 -2.54,0; 9 0,0; 10 2.54,0; 11 5.08,0; 12 7.62,0; 13 10.16,0; 14 12.7,0; 15 15.24,0; 16 17.78,0; 17 20.32,0
1X10 = drill 1.016 long: 1 -11.43,0; 2 -8.89,0; 3 -6.35,0; 4 -3.81,0; 5 -1.27,0; 6 1.27,0; 7 3.81,0; 8 6.35,0; 9 8.89,0; 10 11.43,0
0204/13 = drill 0.813 octagon: 1 -6.872,0; 2 6.872,0
RING = drill 3 pad 4 round: 1 -3.15,0; 2 3.15,0
TO247BH = drill 1.499 long: D 0,-10.16; G -5.588,-10.16; S 5.588,-10.16 | hole 4.115: 0,9.144
1X01 = drill 1 pad 1.676 octagon: 1 0,0
1X02 = drill 1.016 pad 1.676 long: 1 -1.27,0; 2 1.27,0
SOT23-BEC = smd 1 x 1.4: B -0.95,-1.1; C 0,1.1; E 0.95,-1.1
TO126AV = drill 1 pad 1.27 long: B 2.286,-1.27; C 0,-1.27; E -2.286,-1.27
R2512 = smd 1.8 x 3.4: 1 -3.1,0; 2 3.1,0
0207/10 = drill 0.813 octagon: 1 -5.08,0; 2 5.08,0
R1206 = smd 1.3 x 1.7: 1 -1.55,0; 2 1.55,0
B64Y = drill 0.813 long: A 2.54,0; E -2.54,0; S 0,0
0309/10 = drill 0.813 octagon: 1 -5.08,0; 2 5.08,0
0204V = drill 0.813 octagon: 1 -1.27,0; 2 1.27,0
WIRE = drill 0.813 octagon: 1 -8.25,0; 2 8.25,0
SOT23' = smd 1 x 1.4: B -0.95,-1.1; C 0,1.1; E 0.95,-1.1
EE14 = drill 0.6 pad 1 long: 1 4.25,-5; 2 4.25,5; 3 -4.25,5 | drill 0.6 pad 1.016 long: 4 -4.25,2.5; 5 -4.25,-2.5; 6 -4.25,-5
SOT223 = smd 1 x 2: 1 -2.3,-3.15 | smd 1.5 x 2: 2 0,-3.15; 3 2.3,-3.15 | smd 3.8 x 2: 4 0,3.15
TO92-2MIL = drill 0.6 pad 0.813 long: 1 -2.54,0; 2 0,0; 3 2.54,0

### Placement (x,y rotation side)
1HIDRV  36.88,74.29 90 top
1LODRV  34,96.59 45 top
1LOHI  66.7,-18.5 0 top  (outside the outline)
2HIDRV  33.75,27.75 135 top
2LODRV  33,44 90 top
2LOHI  56.7,-18.5 0 top  (outside the outline)
BLACK2  12,93.5 180 bottom
C1  88,109 0 bottom
C2  40,17 90 top
C3  70,109 180 bottom
C4  51,109 180 bottom
C5  27,153 90 bottom  (outside the outline)
C6  53.5,22 270 top
C7  90,79 0 top
C8  53.75,18 0 top
C9  93,95.5 0 top
C10  45.3,7.8 0 top
C11  36.88,74.29 90 top
C12  33.75,27.75 135 top
C13  53,30.25 270 top
C14  47,69 0 top
C15  39.3,91.2 45 top
C16  40,44 90 top
C17  31,54 270 top
C18  14,63 90 bottom
C19  24,63 180 bottom
C20  23.5,90 180 bottom
C21  43.35,74.3 90 top
C22  39,33 135 top
C23  52,-13 90 top  (outside the outline)
C24  63,-12 270 top  (outside the outline)
CY1  80,51 0 bottom
CY4  80.1,35.3 0 bottom
D1  25.86,31.28 180 top
D2  93,32.6 90 bottom
D3  75,81.7 270 top
D4  93,48.5 90 bottom
D4SN  80,26.6 180 bottom
D4SN1  80,43 180 bottom
D5  29.5,35 0 top
D6  30,82 180 top
D7  33,86 0 top
D8  46.93,32.07 0 top
D9  80,80 90 top
D10  38,68.7 0 top
D13  17.5,44.5 90 top
D14  17.5,104 90 top
D15  25,44 0 top
D16  23.5,100 0 top
D17  24,21 0 top
D18  25.5,72 0 top
D19  31,59 180 top
D20  50,63 90 top
D21  50,59 90 top
D22  52,-19 270 top  (outside the outline)
D23  63,-17.9 270 top  (outside the outline)
FAST  51.5,41 270 top
FUSE  40,56 270 top
HOT1  74.4,10.1 180 top
HOT2  66.8,10.1 180 top
HOT3  61.8,10.1 180 top
HOT4  54.4,9.5 0 top
HVL  66,41 90 top
HVL1  59,24 90 top
HVT1  86.3,89.6 180 top
JDRAIN  94,30 270 top
JDRN1  94,46 0 top
JP1  58,-7 0 bottom  (outside the outline)
JP2  58,-27 180 bottom  (outside the outline)
JP7  58,13 0 bottom
JSORC1  94,51.08 0 top
JSOURCE  94,35.08 270 top
L1  62,139 90 bottom  (outside the outline)
L2  62,139 270 bottom  (outside the outline)
M1  2,46.5 90 top
M2  2,109.5 90 top
M3  2,16 90 top
M4  2,77.5 90 top
MAS1  75,75 270 top
MAS2  75,72 90 top
MINUS  60,107 270 bottom
NTC  39.9,5.9 180 bottom
P+1  91,75 270 top
P+2  91,72 90 bottom
PLUS  95,105 270 bottom
Q1  0,46.5 90 top
Q2  0,109.5 90 top
Q3  0,16 90 top
Q4  0,77.5 90 top
Q5  34.2,15.1 135 top
Q10  36,64.5 90 top
Q11  32,12 0 top
R1  22,39.25 180 top
R2  35,7 180 top
R3  82.3,95.5 270 top
R4  83,90 90 top
R4SN  79.8,30 0 bottom
R4SN1  80,46 0 bottom
R5  22,17 0 top
R6  91.6,90.2 0 top
R7  20.5,104 270 top
R8  85,81 270 top
R9  92.5,8 0 top
R10  87.2,17.5 270 top
R11  94.3,86.9 90 top
R12  88,11 270 bottom
R13  82.9,78.9 270 top
R14  79.3,90.1 180 top
R15  23,68 0 top
R16  22,96 180 top
R17  95,112 90 bottom
R19  37,60.75 270 top
R20  31,63 0 top
R21  41,62 0 top
R22  44.3,51.6 180 top
R23  34,59 90 top
R24  34,54 90 top
R25  40.9,22 270 top
R26  42.9,22 270 top
R27  97,9.4 90 top
R28  92,12.7 270 top
R29  90,17.5 270 top
R30  20,73.5 270 top
R31  19,22 270 top
R32  20.5,44.5 270 top
R33  34,96.59 135 top
R34  36.88,74.29 180 top
R35  33,44 180 top
R36  33.75,27.75 225 top
R37  39,-13 90 bottom  (outside the outline)
R38  60.4,-10.8 270 top  (outside the outline)
R39  55.5,-10.8 270 top  (outside the outline)
R40  73.3,-10.8 270 top  (outside the outline)
R41  65.6,-10.8 270 top  (outside the outline)
RED1  not placed on the board
ROUT5  24,49 180 top
ROUT6  22,27 180 top
ROUT7  33,104 0 top
ROUT8  22,80 180 top
RSENS  32,118 180 bottom
SLOW  52,80 270 top
T3  BC848  [SOT23']  74.4,93.8 0 top
TRAFO  85,90 90 bottom
V12_1  83,75 270 top
V12_2  83,72 90 top
VENT  28,6 0 bottom
VREG  47.5,23 0 top
VREG1  47.8,16.1 0 top

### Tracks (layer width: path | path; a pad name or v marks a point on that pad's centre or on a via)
1HO  (via drill 0.6 pad 1.5)
  Top 0.5: D20.1 52.95,62.05 v53,62 | HOT2.2 65.7,12.92 JP7.6 65.6,14.4 65.6,16.4 64,18 64,52.5 63.5,53 v63.5,62 63.5,73 62,74.5 62,78 60.63,79.36 SLOW.12
  Bottom 0.5: v63.5,62 v53,62
1LO  (via drill 0.6 pad 1.5)
  Top 0.5: D21.1 52,58.05 v53,58 | HOT1.2 73.3,12.94 JP7.3 73.24,15.76 73,16 68,21 v68,58 68,79 66,81 65.09,81.91 SLOW.14
  Bottom 0.5: v68,58 v53,58
1LO2HO  (via drill 0.6)
  Top 0.5: 1LOHI.3 68,-23.7 67,-24.7 67,-25 | 67,-25 67,-25.89 JP2.9 | v58,-23.4 56.83,-22.33 56.73,-22.23 2LOHI.2 | v66.9,-25 67,-25
  Bottom 0.5: v58,-23.4 64.6,-23.3 66,-24 v66.9,-25
2HO
  Top 0.5: HOT4.2 55.5,12.96 JP7.10 55.5,14.8 57.5,17 57.5,21 57,22 57,30 61,34 61,40 58.63,40.37 FAST.12
2LO
  Top 0.5: HOT3.2 60.7,12.84 JP7.8 60.54,14.54 62.5,16 62.5,42 60.91,42.91 FAST.14
6YU
  Top 0.5: R34.1 39.06,73.66 1HIDRV.2 | 1HIDRV.2 1HIDRV.3 | SLOW.8 47.4,74.4 47,74 40,74 40,73.87 1HIDRV.2
12V  (via drill 0.6)
  Top 0.5: 49.11,-10.89 49.32,-10.06 JP1.12 | 49.11,-21 49.51,-21.4 | 1LOHI.1 64.04,-20.84 D23.A 63.7,-20.3 v64.5,-20 | v49.11,-20 v49.1,-20 | D22.A 52.6,-21.4 53,-21 55.39,-21 2LOHI.1
  Top 1: JP2.2 49.11,-21 v49.11,-20 49.11,-10.89 | 49.51,-21.4 D22.A
  Bottom 0.5: v49.1,-20 v64.5,-20
A
  Top 0.5: D9.A TRAFO.6
ACL  (via drill 0.6 pad 1.5)  (1 unrouted)
  Top 0.5: R27.2 v97,14
  Route2 0.406: v97,14 97,19
  pour Top: 66,138 66,129 24,129 24,139 25,140 48,140 51,137
ASG
  Top 0.5: 68,-10.8 1LOHI.6 | 68,-10.8 68,-7.16 JP1.5 | C24.1 63.45,-10.45 64,-10.8 68,-10.8
B1C2
  Top 0.5: R6.1 88.05,91.7 HVT1.1 87.45,95.55 86,97 82.9,97 | 82.7,97 R3.1 82.9,97 | T3.C 75.6,96.6 76,97 82.7,97 | 82.9,97 82.7,97
  pour Top (isolate 2): 88,92 88,97 73,97 73,94 86,94 86,92 89,89 91,89 91,91
BLACK  (via drill 0.6 pad 1.5)
  Top 0.5: M4.S Q4.S | R30.1 20.9,77.15 ROUT8.2 19,79.1 19,80 16,83 v14,87 | v66,44 HVL.2
  Route2 0.5: C18.2 14.54,65.54 16,67 16,87 | v66,44 76,68 63,75 44,75 40,79 25,79 22,82 16,87 | 16,87 v14,87 | C5.2 12.72,166.72 -1,153 -1,115 4,110 10,110 10.5,109.5 | 10.5,109.5 11,109 | 10.5,109.5 Q2.D
  Bottom 0.5: M2.D 14.5,109.5 16,108 | 16,84 v14,87 11,83
  other vias: 12,87
  pour Bottom (isolate 2): 12.2,110.3 16.8,110.2 arc-41 17.4,100.5 17,100 17,82 12,82 12,83 11,84 11,105 12,106
  pour Top: 25,171 32,171 35,168 35,144 34,143 25,143
BT1
  Top 0.5: T3.B 73,90.75 73,86.2 74.8,85.2 D3.C 75.4,85 76.9,86.3 77.2,86.7 78,88.3 77.8,88.8 R14.2
  pour Top (isolate 1.5, rank 2): 80,90 80,88 76,84 73,84 73,93 75,93 75,92 77,90
C1
  Top 0.5: HVT1.3 86.3,87.7 87,87 87,86.25 TRAFO.4
COM1
  Top 0.5: ROUT5.1 28,49 30,46 29.77,46 2LODRV.5 35.91,45.91 36,46 36.23,46 2LODRV.4 40.64,45.91 C16.2 43.55,45.55 45,47 49,47 50,46 50,44.5 49.83,44.17 FAST.2
COM2
  Top 0.5: 41,93 44,90 46,90 50,86 50,84 49.17,83.17 SLOW.2 | 41,93 38.42,95.58 1LODRV.4 37.7,97.3 35,100 33.28,100 1LODRV.5 34,101.28 35,101 ROUT7.2 | C15.2 40.4,92.4 41,93
DFG
  Top 0.5: JP7.9 58,15 59,16 HVL1.1
DFTY
  Top 0.5: 1LOHI.8 65.05,-14.6 D23.K C24.2
DIS
  Top 0.5: R19.2 37.5,58.8 FUSE.1
DR2
  pour Top (isolate 2, rank 2): 95,48 81,48 81,41 95,41
  pour Bottom (isolate 2, rank 2): 95,48 81,48 81,41 95,41
DRAIN
  pour Top (isolate 2, rank 2): 95,32 81,32 81,25 95,25
  pour Bottom (isolate 2, rank 2): 95,32 81,32 81,25 95,25
EB
  Top 0.5: R14.1 81.3,91.1 R4.2 84.95,91.1 HVT1.2
ET
  Top 0.5: 36.12,94.46 35.84,94.75 R33.1 46.14,84.44 SLOW.1 | 1LODRV.3 36.59,94.46 36.12,94.46 | 1LODRV.2 36.12,94 36.12,94.46
GAT1
  Top 0.5: R32.2 22.25,42.95 D15.C
  pour Top (isolate 2): 9,42 17,42 17,44 24,44 22,38 9,38
GAT1RD
  Top 0.5: 28,44 29.77,44 | 28,44 25.81,41.81 R1.1 | 2LODRV.6 29.67,44.09 29.77,44 | 29.77,44 29.77,43.46 2LODRV.7 | 28,44 D15.A | 29.77,44 R35.2
GAT2
  Top 0.5: R7.2 20.85,101.45 D16.C | D14.C 12.3,102.3 12,102 12,104 12.07,104 M2.G
  pour Top (isolate 2, rank 2): 8,105 14,105 21,103 24,103 24,97 15,97 13,102 8,102
GAT2RD
  Top 0.5: 32.09,98.49 R33.2 | 32.09,98.49 1LODRV.7 31.2,98.8 30,100 D16.A 25.1,100 R16.1 | 32.09,98.49 1LODRV.6 | 1LODRV.6
GAT3
  pour Top (isolate 2, rank 3): 9,12 9,9 18,9 21,12 21,18 23,22 18,20 18,12
GAT3RD
  Top 0.5: 28,22 30.95,24.95 | 30.95,24.95 2HIDRV.6 | 30.95,24.95 31,25 | 31,25 R36.2 | 2HIDRV.7 31.05,24.95 31,25
  pour Top (isolate 1.5, rank 2): 28,25 35,28 32,23 29,23 28,22 26,17 25,17 25,22 26,22
GAT4
  Top 0.5: Q4.G 12.07,70 14,70 | 17.62,67.95 R30.2 20.75,71.95 D18.C | 17.39,68.18 17.62,67.95 | R15.1 18.9,66.9 19,67 18.57,67 17.62,67.95
  pour Top (isolate 1.5): 8.9,72.5 12.9,72.5 15,71 18,71 19,70 19,69 18,68 15,68 14,69 12,69 11,70 9,70
GAT4RD
  Top 0.5: 33.55,74.29 1HIDRV.7 | 33.55,74.29 1HIDRV.6 | 27,69 29.81,72.88 31.22,74.29 33.55,74.29 | 27,69 D18.A | R15.2 26.1,69.1 27,69 | 33.55,74.29 R34.2
GND
  Top 0.5: 2LOHI.4 59.54,-22.24 59.6,-23 60,-25 59,-25 59,-26.73 JP2.6 | JP1.11 53,-7.08
  pour Top (isolate 1): 33,-1 83,-1 83,-31 33,-31
  pour Bottom (isolate 1): 33,-1 83,-1 83,-19 33,-19
IFB  (via drill 2 pad 1.5)
  Top 0.5: D14.A 20.35,105.7 R7.1 | 20,51.1 ROUT5.2 20,49 19,48 20.5,46.5 R32.1 | 27,63 R20.1 | v26.5,105 ROUT7.1 | JP1.1 78.32,-22.68 74,-27 JP2.10
  Route2 0.5: JP1.1 78.32,-2.32 77,-1 6,-1 5,0 5,49 8,52 10.07,52 Q1.S
  Bottom 0.5: v26.5,105 26.5,90.46 C20.2
  Bottom 3: v26.5,60 v26.5,105
  pour Top (isolate 2, rank 2): 9,51 9,54 10,54 12,56 18,64 27,64 27,55 22,52 22,46 15,46 15,51
  pour Top: 9,121 29,121 29,105 18,105 17,106 17,112 16,113 10,113 9,114
  pour Bottom (rank 4): 9,121 30,121 30,113 10,113 9,114
JDH
  Top 0.5: JP7.5 68,13.16 68,17 66,19 66,39 HVL.1
LIN
  Top 0.5: 61.81,-23.3 61.91,-23.11 60.8,-22 60.8,-18.7 58,-18.7 2LOHI.3 | 61.81,-23.3 JP2.7 | 1LOHI.2 66.73,-22.27 66,-23.3 61.81,-23.3
MASS  (via drill 0.6 pad 1.5)
  Top 0.5: C7.- 91.55,81.45 88.7,82.4 85.8,82.4 R8.1 84.9,82.1 v83.6,83.3 | C9.2 94.1,95.1 v95.4,93.8 | TRAFO.5 82.5,86.5 83,87 R4.1 | v75.7,90.2 75.7,92.35 T3.E | 42,110 42,112 | 53,109 C4.- 59,109 60,108 60,98 | 42,108 42,110 | 42,110 RSENS.2 | 34,37.4 v34,38 31.9,35.9 D5.A | 55.3,19.7 55,20 | FUSE.4 37.4,52.4 37,52 | FAST.15 58.18,44.17 59,45 59,49 v58,50 | D7.A 35.4,83.6 v36,83 | SLOW.15 59.18,83.17 60,84 60,88 59,89 55,89 53,87 53,83 54,83 | JP7.13 47.84,16.06 VREG1.2
  Bottom 0.5: v75.7,90.2 76,76 MAS1.1 | v95.4,93.8 95.4,92.4 95,92 | 83,83 v83.6,83.3 | v34,38 36,40 36,66 39,69 39,80 v36,83 56,103 | 60,99 MINUS.1
  other vias: 57,64 57,71 55,71
  pour Bottom (isolate 2): 96,97 96,73 73,73 73,97
  pour Top (isolate 2, rank 5): 96,97 96,73 73,73 73,97
  pour Bottom (isolate 1, rank 4): 40,80 60,100 99,100 99,22 89,12 89,4 29,4 29,14 44,28 46,30 46,38 40,38
  pour Top (isolate 1, rank 4): 43,84 59,100 100,100 98,23 88,4 26,4 26,10 46,30 51,30 51,34 51.5,34 51.5,49 33,49 30,53
  pour Bottom (isolate 2, rank 3, no thermals): 32,101 32,121 41,121 44,119 44,108 45,107 51.8,107 54,110 62,110 62,107 71,107 71,110 86,110 87,109 87,101
  pour Top (isolate 2, rank 2): 32,121 44,121 44,108 45,107 54,107 54,110 62,110 62,107 71,107 71,110 86,110 87,109 87,101 41,101 32,110
N$1
  Top 0.5: Q5.3 33.02,14.02 32.4,12.4 32.4,11.13 Q11.C 31.9,10.63 31.9,9.4 29.27,6.77 VENT.1
N$2
  Top 0.5: Q5.1 35.45,12.29 Q11.B | Q11.B 34.02,10 | R2.2 33.9,8.9 34,9 34,10.44 Q11.B
N$3
  Top 0.5: JP7.17 37.68,11.68 37,11 37,9 36,8 36,7.1 R2.1
N$4
  Bottom 0.406: 86,90 87,90
N$5  (1 unrouted)
N$6
  Top 0.5: TRAFO.1 81.95,94.25 R3.2
N$7
  Top 0.5: C9.1 91.15,94.3 TRAFO.2
N$8
  Top 0.5: R11.2 94.2,90.15 R6.2
N$9  (via drill 0.6 pad 1.5)
  Top 0.5: R21.1 39.9,60.1 v39.5,60 40,57 39.64,56.63 FUSE.2 | FUSE.5 42.5,54 41,54 v39.5,52 40.4,52.6 R22.2
  Bottom 0.5: v39.5,52 v39.5,60
N$10
  Top 0.5: R8.2 84.8,80.1 R13.1 D3.A
N$12
  Top 0.5: FAST.8 42.56,36.55 36,30 | 35.66,29.66 36,30 | 2HIDRV.3 35.66,30.34 36,30 | 35.66,29.66 2HIDRV.2 | R36.1 35.66,29.66
N$14
  Top 0.5: R20.2 32.1,60.25 D19.1
N$15
  Top 1: R40.1 73.3,-7.06 JP1.3
N$16
  Top 0.5: 36,44 38,44 38.26,43.74 39.74,43.74 40,44 44,44 45.44,45.45 FAST.1 | 36,44 36,44.2 | 36,44.2 35.9,43.97 | 2LODRV.2 36.33,43.67 36,44 | 36,44.2 36,44 | 2LODRV.3 36.33,44.53 36,44.2 | R35.1 36,44
N$17
  Top 0.5: R25.2 R26.2 43.1,20.8 44.4,20.8 45.2,20 VREG.1
N$18
  Top 0.5: Q10.E 39.8,64.25 47.6,64.25 D20.3 D21.3
N$19
  Top 0.5: 1LOHI.7 66.73,-13.1 R41.2
N$20
  Top 0.5: D1.C 27.1,32.7 D5.K
N$21
  Top 1: R38.1 60.5,-7.04 JP1.8
N$22
  Top 0.5: 69,-19 69,-17
N$23
  Top 0.5: R27.1 94.2,7.85 R9.2
N$24
  Top 0.5: D6.C 31.7,84.9 D7.K
N$25
  Top 0.5: Q10.B 36.95,62.05 R19.1
N$26
  Top 0.5: R23.2 34,61.9 Q10.C
N$27
  Top 1: R39.1 55.5,-7.04 JP1.10
N$29
  Top 0.5: R28.1 92,15 91,16 90.4,16 R29.2 R10.2 88,15.6 R12.E
N$30
  Top 0.5: R12.A 90.49,8.46 R9.1 91,8.05 91,10 92,11 R28.2
N$32
  Top 0.5: 2LOHI.5 60.01,-14.49 60,-14 60,-12.47 R38.2
N$33
  Top 0.5: 2LOHI.7 56.73,-13.1 R39.2
N$34
  Top 1: R41.1 65.6,-7.02 JP1.6
N$35
  Top 0.5: 1LOHI.5 72.38,-14.69 R40.2
O_IFB  (via drill 0.6 pad 1.5)
  Top 0.5: C17.1 D19.3 R23.1 R24.2 34.27,55.37 FUSE.3 FUSE.6 44.64,55.37 v48,53 | v78,16 78,13.32 JP7.1
  Bottom 0.5: v48,53 69,53 70,52 70,24 v78,16
PUMP+
  Top 0.406: P+2.1 P+1.1
  Top 0.5: P+1.1 94,75 95,76 95,83 94.65,84.35 R11.1 90.4,85.35 TRAFO.3 | P+2.1 91,73 91.38,73.27 | C4.+ 48.46,114 | M4.D Q4.D
  Bottom 0.5: C1.+ 89,106 89,101 97,101 98,100 98,74 96,72 P+2.1 | 20,78 20,88 19.46,88.54 C20.1 | 20,78 15,78 | 17,77.5 20,77.5 | M4.D 17,77.5 | 17,77.5 20,78 | M3.D 23,16 23,54 22.54,54.46 C19.1
  pour Top (isolate 2, rank 2): 95,86 95,73 91,73 91,77 94,77 94,84.6 90,84.6 90,86
  pour Bottom (isolate 2, rank 2): 44,121 98,121 98,108 89,108 85,112 72,112 69,109 69,108 66,108 66,110 64,112 51,112 50,111 50,108 24,108 23,107 23,84 19,84 19,99 20,101 20,112 43,112 44,113
  pour Top (isolate 2, rank 4): 46,121 98,121 98,108 89,108 85,112 72,112 69,109 69,108 66,108 66,110 64,112 51,112 50,111 50,108 23,108 22,107 17,109 20,112 43,112 44,113
  pour Bottom (isolate 2, rank 2): 9,18 19,18 19,74 18,76 15,76 13,78 15,80 18,80 19,81 19,90 20,91 21,91 24,88 26,52 26,16 23,13 10,13 9,14
RED  (via drill 0.6 pad 1.5, 2.2 pad 1.5)  (1 unrouted)
  Top 0.5: v59,26 HVL1.2 | R31.1 17.45,23.55 v15,26 | M1.D Q1.D
  Route2 0.5: L2.1 L1.2 | v15,26 35,24 36,23 57,27 59,25 v59,26
  other vias: 12,30
  pour Top (isolate 2): 10,21 10,35 18,35 18,24 19,24 17,22 15,22 14,21
  pour Bottom (isolate 2): 11,60 15,60 17,55 17,50 20,48 20,20 10,20 10,35 16,41 11,48 15,48 15,56 11,57
SCR2
  pour Top (isolate 2): 95,53 95,50 81,50 81,53
  pour Bottom (isolate 2): 95,53 95,50 81,50 81,53
SD  (via drill 0.6 pad 1.5)
  Top 0.5: FAST.13 54.37,41.63 53.5,42 53.5,55 48.27,55 48.27,55.73 v48,56 47.36,56.63 FUSE.7 | SLOW.13 63.37,80.64 66,78 v66,55
  Bottom 0.5: v48,56 50,56 51,55 v66,55
SERT
  Top 0.5: 58,-10.9 2LOHI.6 | 58,-10.9 JP1.9 | C23.2 52.85,-11.45 53.8,-10.8 57.6,-10.8 58,-10.9
SNUB1
  pour Top (isolate 2, rank 2): 79,53 79,41 72,41 72,53
  pour Bottom (isolate 2, rank 2): 79,53 79,41 72,41 72,53
SNUB2
  pour Top (isolate 2, rank 2): 79,37 79,25 72,25 72,37
  pour Bottom (isolate 2, rank 2): 79,37 79,25 72,25 72,37
SOURCE
  pour Top (isolate 2): 95,37 95,34 81,34 81,37
  pour Bottom (isolate 2): 95,37 95,34 81,34 81,37
TFB  (via drill 0.6 pad 1.5)
  Top 0.5: C2.1 40,13.22 JP7.16 40,12.78 v40,11 | NTC.1 38.63,7.63 v38.6,8.1
  Top 1: JP1.16 40.22,-9.78 40,-10 39,-10 | 39,-10 37,-10 37,-7.68 JP1.17 | R37.2 39,-10
  Route2 0.5: JP1.17 37.68,4.95 NTC.1
  Bottom 0.5: v38.6,8.1 38.6,9.6 v40,11
V12  (via drill 0.6 pad 1.5)
  Top 0.406: 49.4,31.5 49.4,31.6 v51.8,34
  Top 0.5: C7.+ 88.45,77.45 87,76 84,76 V12_1.1 | V12_1.1 R13.2 | D9.K 80,78 V12_1.1 | 37,41 41,41 C16.1 41.55,42.45 v42.4,41.2 43.5,41.2 45.2,42.9 45.7,42.91 FAST.3 | 37,41 30,41 | 30,41 29.69,41 | FUSE.8 42.69,58.7 v42,60 42.1,60.6 R21.2 | 82.17,73 82,73 82,72 V12_2.1 83,67 v72,67 | v50.3,10.5 50.3,12.92 JP7.12 | JP7.12 50.2,13.18 | JP7.12 50.34,13.04 VREG1.3 50.3,16.14 50.3,16.8 50,17.1 50,18 | VENT.2 26.73,6.27 v26.7,8.7 | 2LODRV.8 29.67,41.33 30,41 | 2LODRV.1 36.33,41.67 37,41 | 1LODRV.8 30.3,96.89 30.46,96.73 30.46,95.88 32.94,93.4 33.29,93.4 33.29,93.05 34,92.34 34.47,92.34 1LODRV.1 36,91.89 36,91 37.5,89.5 | VREG.3 49.8,18.2 50,18 | C8.+ 50.1,17.9 50,18 | D8.A 49.4,31.5 49.9,31.5 49.9,31.7 | SLOW.3 45.09,81.91 43,84 | 43,84 37.5,89.5 | C15.1 38.1,90.1 37.5,89.5 | C13.1 53,32 52,34 52,33.4 v51.8,34 | D10.A 40.4,68.6 v42,67 43.45,67 C14.1 | v42,82 42,83 43,84
  Bottom 0.406: 42,41.2 v42.4,41.2 | 42,41.2 42,41.6 | 42,20 42,34 | 42,34 42,41.2 | 42,20 48,20 | 42,20 35,20 31,16 | 42,34 v51.8,34
  Bottom 0.5: v42,67 v42,60 42,42 v42.4,41.2 | v42,67 v42,82 | 48,20 50.1,17 50.3,16.8 v50.3,10.5 | v42,67 v72,67 | v26.7,8.7 27,9 27,12 31,16
  pour Top (isolate 2): 89,79 89,73 80,73 80,78 87,78
VB1
  Top 0.5: SLOW.7 49.17,76.83 50,76 50,74 49,73 43.6,73 C21.1 43.24,71.89 43.24,71.24 43,71 42.49,71.51 40.21,71.51 1HIDRV.1 | 1HIDRV.8 33.55,71.45 34,71 | D10.K 35.6,69.6 36,70
  pour Top (isolate 1.5): 32,72 43,72 43,71 39,71 38,70 37,69 32,69
VB2
  Top 0.5: 39.18,29 40,29 41,30 | 41,30 42,31 41.99,31.01 | 41,30 42.4,31 D8.K 44.5,32.5 45,35 49.5,35 49.5,37.5 49.2,37.8 48.83,37.83 FAST.7 | 2HIDRV.1 37.45,28.55 38,28 | 2HIDRV.8 32.95,24.05 34,23
  pour Top (isolate 1.5): 33,23 34,22 43,31 43,33 42,33 33,24
VBH
  Top 0.5: 2LOHI.8 52.14,-14.69 C23.1 D22.K
VDD  (via drill 0.6 pad 1.5)
  Top 0.5: 47.9,23.1 R26.1 | 47.9,23.1 48,23 48,21.6 47.6,21.2 47.6,19 46.4,17.8 45.5,17.8 45.26,17.56 VREG1.1 45.3,16.06 JP7.14 45.3,11.3 v45.4,10.7 | VREG.4 47.5,23.5 47.9,23.1 | v41.2,8 41,6.07 NTC.2 | FAST.11 57.91,39.09 59,39 59,36 v58,35 | v52,24 C6.+ | SLOW.11 57.91,78.09 60,76 60,72 61,71 v61,51
  Route2 0.5: JP1.14 45.3,-1.3 41,3 41,5.73 NTC.2
  Bottom 0.5: v45.4,10.7 45.4,10.6 v41.2,8 | v52,24 56,28 56,33 v58,35 61,38 v61,51
  pour Top (isolate 0.8): 45,25 53,25 53,24 51,20 49,20 49,19 46,15 43,15 43,23
VFB  (via drill 0.6)
  Top 0.5: R12.S 86,11 82,5 49,5 44.2,5.2 C10.1 42.76,9.84 JP7.15 | v55,-23.8 55.3,-24.23 JP2.5
  Top 1: v42.76,-22.76 JP1.15
  Route2 0.5: JP1.15 42.76,0.76 46,4 46,6.4 43.24,9.17 43.24,12.52 JP7.15
  Bottom 0.5: v42.76,-22.76 51.76,-22.76 v55,-23.8
VS3
  Top 0.5: ROUT6.1 25.25,28.1 | 25.25,28.1 25.3,28.51 | 2HIDRV.4 34.55,31.45 34,32 | FAST.6 42.09,39.09 39,36 38.81,35 C22.2 | 2HIDRV.5 30.05,26.95 29,28 | 29,28 29.9,28 C12.2 | 29,28 25.35,28 25.25,28.1
  pour Top (isolate 1.5): 24,32 26,32 29,29 30,29 36,35 42,35 42,34 38,34 31,27 28,26 24,29
VS4
  Top 0.5: 1HIDRV.5 33.34,76.4 33.34,77 33,77 | SLOW.6 44.09,78.09 43,77 43,76.2 | 43,76.2 C21.2 | 33,77 27,77 ROUT8.1 27.1,82 D6.A | 43,76.2 1HIDRV.4 39.21,77.19 C11.2 33.19,77.19 33,77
